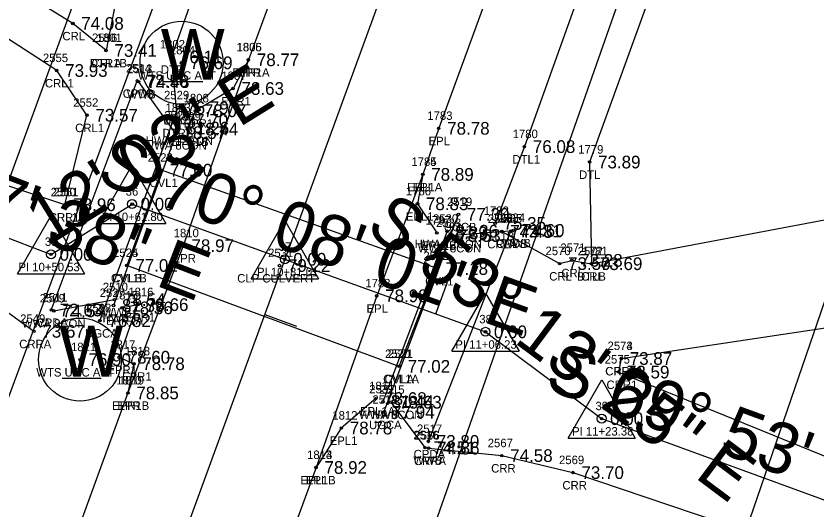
# Model space of a CAD drawing. Extents: x 2139392 to 2143384, y 505395 to 510520.
# Drawn here: x 2140931.1 to 2141025.8, y 509038.2 to 509096.6 of the extents above; entities that cross this region are included whole.
import ezdxf

# ---------------------------------------------------------------- set-up
doc = ezdxf.new("R2010")
doc.units = 0
for name, color, linetype in [('RD_EV_EX_Wetlands', 7, 'Continuous'), ('RD_EX_Bridge', 7, 'Continuous'), ('RD_EX_Bridge_txCode', 7, 'Continuous'), ('RD_EX_Conc', 7, 'Continuous'), ('RD_EX_Conc_txCode', 7, 'Continuous'), ('RD_EX_H2O', 7, 'Continuous'), ('RD_EX_H2O_txCode', 7, 'Continuous'), ('RD_EX_Road', 7, 'Continuous'), ('RD_EX_Road_txCode', 7, 'Continuous'), ('RD_EX_TX_Bridge_ELEV', 7, 'Continuous'), ('RD_EX_TX_Conc_ELEV', 7, 'Continuous'), ('RD_EX_TX_H2O_ELEV', 7, 'Continuous'), ('RD_EX_TX_Road_ELEV', 7, 'Continuous'), ('RD_EX_TX_UT_ELEV', 7, 'Continuous'), ('RD_EX_UT', 7, 'Continuous'), ('RD_EX_UT_txCode', 7, 'Continuous'), ('RD_EX_VEG', 7, 'Continuous'), ('RD_HC_Cl', 7, 'Continuous'), ('RD_HC_Data', 7, 'Continuous'), ('RD_HC_Data_Tic', 7, 'Continuous'), ('RD_HC_Survey_ELEV', 7, 'Continuous'), ('RD_HC_Survey_txCode', 7, 'Continuous'), ('RD_HC_txCode', 7, 'Continuous'), ('RD_SMD_Locator', 7, 'Continuous')]:
    doc.layers.add(name, color=color, linetype=linetype)

msp = doc.modelspace()

# ---------------------------------------------------------------- linework, layer by layer
at = {"layer": 'RD_EV_EX_Wetlands'}
for p, q in [((2141031.306, 509324.164), (2140691.527, 508408.628)), ((2141075.304, 509306.136), (2140751.402, 508384.33))]:
    msp.add_line(p, q, dxfattribs=at)
at = {"layer": 'RD_EX_Bridge'}
for p, q in [((2140949.87, 509082.827), (2140945.533, 509088.869)), ((2140950.236, 509083.385), (2140942.575, 509062.4)), ((2140982.027, 509071.179), (2140974.443, 509051.015)), ((2140982.335, 509070.674), (2140989.888, 509071.278)), ((2140976.362, 509055.202), (2140944.155, 509067.133)), ((2140935.526, 509061.759), (2140942.697, 509063.091)), ((2140975.368, 509050.963), (2140979.412, 509045.581))]:
    msp.add_line(p, q, dxfattribs=at)
msp.add_lwpolyline([(2140976.362, 509055.202), (2140980.845, 509066.769), (2140948.243, 509078.401), (2140944.155, 509067.133)], dxfattribs=at)
at = {"layer": 'RD_EX_Conc'}
for p, q in [((2140935.225, 509061.866), (2140945.395, 509088.954)), ((2140979.81, 509046.325), (2140989.555, 509071.198))]:
    msp.add_line(p, q, dxfattribs=at)
at = {"layer": 'RD_EX_H2O'}
for points in [[(2141109.57, 509415.73), (2141114.373, 509420.617), (2141120.575, 509418.468), (2141123.731, 509414.719), (2141106.652, 509363.278), (2141087.87, 509318.683), (2141079.163, 509303.209), (2141069.29, 509273.889), (2141065.763, 509268.541), (2141032.314, 509171.571), (2140998.874, 509079.361), (2140999.098, 509067.338)], [(2141109.57, 509415.73), (2141094.185, 509368.738), (2141059.481, 509270.332), (2141024.495, 509174.17), (2140991.165, 509081.187), (2140987.702, 509072.107)], [(2141025.18, 509330.004), (2141009.078, 509287.11), (2140976.481, 509188.975), (2140943.34, 509100.907), (2140941.691, 509092.552)], [(2141025.18, 509330.004), (2141033.423, 509326.189), (2141034.031, 509320.599), (2141020.737, 509281.868), (2140983.567, 509187.835), (2140949.439, 509091.794), (2140950.117, 509084.291)], [(2140936.82, 509074.317), (2140939.438, 509084.9), (2140935.86, 509090.184), (2140919.454, 509100.866), (2140920.422, 509116.79)], [(2140941.691, 509092.552), (2140937.766, 509095.748), (2140924.442, 509103.995), (2140920.422, 509116.79)], [(2140936.82, 509074.317), (2140923.191, 509078.832), (2140898.915, 509091.534), (2140893.323, 509095.681)], [(2140933.167, 509059.343), (2140914.479, 509072.895), (2140897.142, 509089.506), (2140893.323, 509095.681)], [(2140988.496, 509071.154), (2140995.331, 509067.351), (2140996.764, 509067.733), (2140999.098, 509067.338), (2141034.377, 509073.973), (2141067.924, 509085.443), (2141090.438, 509074.609), (2141110.471, 509071.641), (2141125.768, 509059.81), (2141130.362, 509054.364)], [(2141002.624, 509056.131), (2141033.302, 509060.757), (2141063.489, 509073.164), (2141074.877, 509066.766), (2141067.89, 509053.225), (2141068.088, 509037.895), (2141072.636, 509017.092)], [(2141002.624, 509056.131), (2141002.292, 509054.528), (2141039.776, 509039.252), (2141058.736, 509017.843), (2141072.636, 509017.092)], [(2140979.842, 509045.531), (2140988.486, 509044.646), (2140996.911, 509042.641), (2141034.466, 509029.98), (2141054.864, 509009.953), (2141076.501, 509008.6), (2141108.933, 509002.878), (2141157.173, 508989.85), (2141167.478, 508991.008), (2141188.812, 509012.46), (2141188.278, 509016.578)]]:
    msp.add_lwpolyline(points, dxfattribs=at)
at = {"layer": 'RD_EX_Road'}
for points in [[(2141086.274, 509371.268), (2141050.416, 509272.831), (2141015.083, 509176.386), (2140981.032, 509083.349), (2140979.152, 509077.9), (2140973.702, 509063.543), (2140966.529, 509043.246), (2140933.444, 508952.985), (2140896.921, 508852.594), (2140862.176, 508757.775), (2140824.897, 508656.318), (2140789.814, 508560.303), (2140766.773, 508496.85), (2140751.904, 508457.035), (2140731.87, 508401.538), (2140727.357, 508390.267)], [(2141052.52, 509348.478), (2141043.476, 509323.884), (2141027.845, 509280.545), (2140992.949, 509184.866), (2140958.528, 509091.45), (2140950.798, 509069.471), (2140944.28, 509052.058), (2140911.452, 508962.099), (2140874.646, 508861.605), (2140839.422, 508765.216), (2140802.376, 508664.564), (2140767.791, 508569.67), (2140744.17, 508504.83), (2140729.493, 508465.071), (2140707.156, 508404.621), (2140705.357, 508398.025)], [(2140958.528, 509091.45), (2140956.714, 509088.061), (2140952.259, 509085.423), (2140951.313, 509083.254)], [(2140979.152, 509077.9), (2140978.521, 509074.421), (2140980.815, 509070.975)], [(2140943.562, 509062.114), (2140945.418, 509062.499), (2140943.254, 509056.281), (2140944.985, 509055.507), (2140944.28, 509052.058)], [(2140973.585, 509051.39), (2140969.517, 509047.91), (2140966.529, 509043.246)]]:
    msp.add_lwpolyline(points, dxfattribs=at)
at = {"layer": 'RD_EX_UT'}
for p, q in [((2140948.502, 509088.885), (2140953.131, 509088.885)), ((2140940.967, 509060.604), (2140950.18, 509085.778)), ((2140974.537, 509049.783), (2140983.367, 509073.169)), ((2140936.488, 509053.791), (2140941.117, 509053.791))]:
    msp.add_line(p, q, dxfattribs=at)
for centre in [(2140950.63, 509091.093), (2140938.616, 509055.999)]:
    msp.add_circle(centre, 4.908, dxfattribs=at)
at = {"layer": 'RD_EX_VEG'}
for points in [[(2140900.084, 509397.36), (2141021.293, 509326.195), (2140852.613, 508865.264), (2140689.341, 508413.458), (2140624.535, 508226.483), (2140606.41, 508171.784), (2140591.23, 508116.672), (2140558.821, 507962.773), (2140538.778, 507709.071), (2140410.608, 507724.882)], [(2141197.739, 509262.45), (2141108.657, 509301.696), (2140947.303, 508831.924), (2140798.257, 508440.006), (2140718.897, 508193.899), (2140671.921, 508048.021), (2140772.34, 507989.744)]]:
    msp.add_lwpolyline(points, dxfattribs=at)
at = {"layer": 'RD_HC_Cl'}
for p, q in [((2141333.53, 510081.693), (2140670.514, 508268.365)), ((2140918.963, 509074.69), (2140935.196, 509068.446)), ((2140935.196, 509068.446), (2140944.777, 509074.386)), ((2140944.777, 509074.386), (2140986.562, 509059.288)), ((2140986.562, 509059.288), (2141000.301, 509049.019)), ((2141000.301, 509049.019), (2141036.935, 509035.612))]:
    msp.add_line(p, q, dxfattribs=at)
at = {"layer": 'RD_HC_Data'}
for p, q in [((2140940.806, 509072.094), (2140944.778, 509078.973)), ((2140944.778, 509078.973), (2140948.747, 509072.094)), ((2140931.225, 509066.153), (2140935.197, 509073.033)), ((2140935.197, 509073.033), (2140939.166, 509066.153)), ((2140940.806, 509072.094), (2140948.747, 509072.094)), ((2140958.867, 509065.568), (2140962.839, 509072.447)), ((2140962.839, 509072.447), (2140966.807, 509065.568)), ((2140931.225, 509066.153), (2140939.166, 509066.153)), ((2140958.867, 509065.568), (2140966.807, 509065.568)), ((2140982.591, 509056.995), (2140986.563, 509063.875)), ((2140986.563, 509063.875), (2140990.532, 509056.995)), ((2140982.591, 509056.995), (2140990.532, 509056.995)), ((2140996.33, 509046.726), (2141000.302, 509053.606)), ((2141000.302, 509053.606), (2141004.271, 509046.726)), ((2140996.33, 509046.726), (2141004.271, 509046.726))]:
    msp.add_line(p, q, dxfattribs=at)
for centre in [(2140944.777, 509074.386), (2140935.196, 509068.446), (2140962.837, 509067.861), (2140986.562, 509059.288), (2141000.301, 509049.019)]:
    msp.add_circle(centre, 0.529, dxfattribs=at)
at = {"layer": 'RD_HC_Data_Tic'}
for p, q in [((2140980.701, 509061.406), (2140982.061, 509065.168)), ((2140960.454, 509061.342), (2140964.211, 509059.968))]:
    msp.add_line(p, q, dxfattribs=at)
at = {"layer": 'RD_SMD_Locator'}
for centre in [(2140937.766, 509095.748), (2140941.691, 509092.552), (2140941.691, 509092.552), (2140949.439, 509091.794), (2140950.63, 509091.093), (2140958.528, 509091.45), (2140958.528, 509091.45), (2140935.86, 509090.184), (2140945.395, 509088.954), (2140945.533, 509088.869), (2140956.714, 509088.061), (2140950.18, 509085.778), (2140952.259, 509085.423), (2140939.438, 509084.9), (2140950.117, 509084.291), (2140950.236, 509083.385), (2140951.313, 509083.254), (2140981.032, 509083.349), (2140949.87, 509082.827), (2140991.165, 509081.187), (2140998.874, 509079.361), (2140948.243, 509078.401), (2140979.152, 509077.9), (2140979.152, 509077.9), (2140936.82, 509074.317), (2140936.82, 509074.317), (2140944.777, 509074.386), (2140978.521, 509074.421), (2140983.367, 509073.169), (2140987.702, 509072.107), (2140980.815, 509070.975), (2140982.027, 509071.179), (2140988.496, 509071.154), (2140989.555, 509071.198), (2140989.888, 509071.278), (2140982.335, 509070.674), (2140950.798, 509069.471), (2140935.196, 509068.446), (2140944.155, 509067.133), (2140944.155, 509067.133), (2140962.206, 509067.119), (2140962.837, 509067.861), (2140995.331, 509067.351), (2140996.764, 509067.733), (2140999.098, 509067.338), (2140999.098, 509067.338), (2140980.845, 509066.769), (2140973.702, 509063.543), (2140942.575, 509062.4), (2140942.697, 509063.091), (2140945.418, 509062.499), (2140935.225, 509061.866), (2140935.526, 509061.759), (2140943.562, 509062.114), (2140940.967, 509060.604), (2140933.167, 509059.343), (2140986.562, 509059.288), (2140938.616, 509055.999), (2140943.254, 509056.281), (2141002.624, 509056.131), (2141002.624, 509056.131), (2140944.985, 509055.507), (2140976.362, 509055.202), (2140976.362, 509055.202), (2141002.292, 509054.528), (2140944.28, 509052.058), (2140944.28, 509052.058), (2140973.585, 509051.39), (2140974.443, 509051.015), (2140975.368, 509050.963), (2140974.537, 509049.783), (2141000.301, 509049.019), (2140969.517, 509047.91), (2140979.81, 509046.325), (2140979.412, 509045.581), (2140979.842, 509045.531), (2140988.486, 509044.646), (2140966.529, 509043.246), (2140966.529, 509043.246), (2140996.911, 509042.641)]:
    msp.add_circle(centre, 0.15, dxfattribs=at)

# ---------------------------------------------------------------- texts
at = {"layer": 'RD_EX_Bridge_txCode'}
for s, p in [('2513', (2140944.187, 509089.869)), ('WWB', (2140944.155, 509086.869)), ('2526', (2140948.583, 509084.385)), ('2512', (2140948.524, 509083.827)), ('HWA 12CON', (2140946.394, 509081.385)), ('WWA 8CON', (2140946.106, 509080.827)), ('2523', (2140946.613, 509079.401)), ('CVL1', (2140946.833, 509076.401)), ('2530', (2140980.358, 509072.179)), ('2534', (2140988.258, 509072.278)), ('2533', (2140980.705, 509071.674)), ('HWA 12CON', (2140978.184, 509069.179)), ('WWB', (2140988.51, 509069.278)), ('2524', (2140942.525, 509068.133)), ('2525', (2140942.525, 509068.133)), ('WWA 8CON', (2140978.571, 509068.674)), ('2522', (2140979.215, 509067.769)), ('CVL1B', (2140942.273, 509065.133)), ('CVLB', (2140942.438, 509065.133)), ('CVL1', (2140979.435, 509064.769)), ('2527', (2140940.945, 509063.4)), ('2510', (2140941.311, 509064.091)), ('2509', (2140933.857, 509062.759)), ('WWB', (2140941.319, 509061.091)), ('WWA 8CON', (2140931.762, 509059.759)), ('HWB', (2140941.283, 509060.4)), ('2520', (2140974.693, 509056.202)), ('2521', (2140975.016, 509056.202)), ('CVL1A', (2140974.464, 509053.202)), ('CVLA', (2140974.63, 509053.202)), ('2532', (2140972.813, 509052.015)), ('2515', (2140974.021, 509051.963)), ('WWA 8CON', (2140971.604, 509048.963)), ('HWB', (2140973.151, 509049.015)), ('2516', (2140978.042, 509046.581)), ('WWB', (2140978.034, 509043.581))]:
    msp.add_text(s, height=1, dxfattribs=at).set_placement(p)
at = {"layer": 'RD_EX_Conc_txCode'}
for s, p in [('2514', (2140944.049, 509089.954)), ('CPDB', (2140943.671, 509086.954)), ('2535', (2140987.926, 509072.198)), ('CPDB', (2140987.831, 509069.198)), ('2511', (2140934.162, 509062.866)), ('CPDA', (2140933.485, 509059.866)), ('2517', (2140978.464, 509047.325)), ('CPDA', (2140978.07, 509044.325))]:
    msp.add_text(s, height=1, dxfattribs=at).set_placement(p)
at = {"layer": 'RD_EX_H2O_txCode'}
for s, p in [('CRL', (2140936.538, 509093.748)), ('2556', (2140940.038, 509093.552)), ('1801', (2140940.589, 509093.552)), ('1802', (2140948.053, 509092.794)), ('2555', (2140934.23, 509091.184)), ('DTR1B', (2140939.786, 509090.552)), ('CRLA', (2140939.975, 509090.552)), ('DTR', (2140948.172, 509089.794)), ('CRL1', (2140934.466, 509088.184)), ('2552', (2140937.808, 509085.9)), ('1803', (2140948.731, 509085.291)), ('CRL1', (2140938.044, 509082.9)), ('DTRB', (2140948.376, 509082.291)), ('1780', (2140989.779, 509082.187)), ('1779', (2140997.528, 509080.361)), ('DTL1', (2140989.756, 509079.187)), ('DTL', (2140997.63, 509077.361)), ('2550', (2140935.151, 509075.317)), ('2551', (2140935.474, 509075.317)), ('1782', (2140986.356, 509073.107)), ('CRR1A', (2140934.915, 509072.317)), ('CRL1A', (2140934.938, 509072.317)), ('2568', (2140986.842, 509072.154)), ('DTL1B', (2140985.821, 509070.107)), ('CRLA', (2140986.779, 509069.154)), ('2570', (2140993.661, 509068.351)), ('2571', (2140995.418, 509068.733)), ('2572', (2140997.468, 509068.338)), ('1781', (2140998.035, 509068.338)), ('CRL', (2140994.102, 509065.351)), ('CRL', (2140995.536, 509065.733)), ('DTLB', (2140997.381, 509065.338)), ('CRL', (2140997.87, 509065.338)), ('2549', (2140931.537, 509060.343)), ('CRRA', (2140931.427, 509057.343)), ('2573', (2141000.994, 509057.131)), ('2574', (2141000.994, 509057.131)), ('2575', (2141000.662, 509055.528)), ('CRR1A', (2141000.718, 509054.131)), ('CRL1A', (2141000.742, 509054.131)), ('CRR1', (2141000.875, 509052.528)), ('2566', (2140978.165, 509046.531)), ('2567', (2140986.832, 509045.646)), ('CRRA', (2140978.102, 509043.531)), ('2569', (2140995.258, 509043.641)), ('CRR', (2140987.234, 509042.646)), ('CRR', (2140995.659, 509040.641))]:
    msp.add_text(s, height=1, dxfattribs=at).set_placement(p)
at = {"layer": 'RD_EX_Road_txCode'}
for s, p in [('1806', (2140957.118, 509092.45)), ('1805', (2140957.142, 509092.45)), ('1807', (2140955.328, 509089.061)), ('EPR1A', (2140956.646, 509089.45)), ('EPR', (2140957.299, 509089.45)), ('1808', (2140950.873, 509086.423)), ('EPR1', (2140955.32, 509086.061)), ('1809', (2140949.928, 509084.254)), ('1783', (2140979.686, 509084.349)), ('EPR1', (2140950.865, 509083.423)), ('EPR1B', (2140949.447, 509081.254)), ('EPL', (2140979.828, 509081.349)), ('1784', (2140977.806, 509078.9)), ('1785', (2140977.806, 509078.9)), ('EPL1A', (2140977.294, 509075.9)), ('EPL', (2140977.947, 509075.9)), ('1786', (2140977.151, 509075.421)), ('EPL1', (2140977.151, 509072.421)), ('1787', (2140979.468, 509071.975)), ('1810', (2140949.696, 509070.471)), ('EPL1B', (2140978.972, 509068.975)), ('EPR', (2140949.57, 509067.471)), ('1788', (2140972.355, 509064.543)), ('1816', (2140944.331, 509063.499)), ('1815', (2140942.499, 509063.114)), ('EPL', (2140972.497, 509061.543)), ('EPR1A', (2140941.68, 509060.114)), ('EPR1', (2140944.024, 509060.499)), ('1817', (2140942.191, 509057.281)), ('1818', (2140943.922, 509056.507)), ('EPR1', (2140941.86, 509054.281)), ('1820', (2140942.894, 509053.058)), ('1819', (2140943.217, 509053.058)), ('EPR1', (2140943.592, 509053.507)), ('1811', (2140972.805, 509052.39)), ('EPR1B', (2140942.414, 509050.058)), ('EPR', (2140943.051, 509050.058)), ('EPL1A', (2140971.727, 509049.39)), ('1812', (2140968.454, 509048.91)), ('EPL1', (2140968.147, 509045.91)), ('1813', (2140965.466, 509044.246)), ('1814', (2140965.466, 509044.246)), ('EPL1B', (2140964.686, 509041.246)), ('EPL', (2140965.324, 509041.246))]:
    msp.add_text(s, height=1, dxfattribs=at).set_placement(p)
at = {"layer": 'RD_EX_TX_Bridge_ELEV'}
for s, p in [('74.48', (2140946.533, 509088.119)), ('78.57', (2140950.87, 509082.077)), ('81.26', (2140951.236, 509082.635)), ('77.00', (2140949.243, 509077.651)), ('81.36', (2140983.027, 509070.429)), ('74.60', (2140990.888, 509070.528)), ('78.53', (2140983.335, 509069.924)), ('77.02', (2140945.155, 509066.383)), ('77.02', (2140945.155, 509066.383)), ('77.18', (2140981.845, 509066.019)), ('78.54', (2140943.697, 509062.341)), ('74.54', (2140936.526, 509061.009)), ('81.39', (2140943.575, 509061.65)), ('77.02', (2140977.362, 509054.452)), ('77.02', (2140977.362, 509054.452)), ('81.44', (2140975.443, 509050.265)), ('78.63', (2140976.368, 509050.213)), ('74.51', (2140980.412, 509044.831))]:
    msp.add_text(s, height=1.5, dxfattribs=at).set_placement(p)
at = {"layer": 'RD_EX_TX_Conc_ELEV'}
for s, p in [('72.56', (2140946.395, 509088.204)), ('72.31', (2140990.555, 509070.448)), ('72.63', (2140936.225, 509061.116)), ('73.80', (2140980.81, 509045.575))]:
    msp.add_text(s, height=1.5, dxfattribs=at).set_placement(p)
at = {"layer": 'RD_EX_TX_H2O_ELEV'}
for s, p in [('74.08', (2140938.766, 509094.998)), ('73.41', (2140942.691, 509091.802)), ('73.41', (2140942.691, 509091.802)), ('76.11', (2140950.439, 509091.044)), ('73.93', (2140936.86, 509089.434)), ('73.57', (2140940.438, 509084.15)), ('77.70', (2140951.117, 509083.541)), ('76.08', (2140992.165, 509080.437)), ('73.89', (2140999.874, 509078.611)), ('73.96', (2140937.82, 509073.567)), ('73.96', (2140937.82, 509073.567)), ('75.35', (2140988.702, 509071.357)), ('74.48', (2140989.496, 509070.404)), ('73.28', (2140997.764, 509066.983)), ('73.50', (2140996.331, 509066.601)), ('73.69', (2141000.098, 509066.588)), ('73.69', (2141000.098, 509066.588)), ('73.67', (2140934.167, 509058.593)), ('73.87', (2141003.624, 509055.381)), ('73.87', (2141003.624, 509055.381)), ('73.59', (2141003.292, 509053.778)), ('74.86', (2140980.842, 509044.781)), ('74.58', (2140989.486, 509043.896)), ('73.70', (2140997.911, 509041.891))]:
    msp.add_text(s, height=1.5, dxfattribs=at).set_placement(p)
at = {"layer": 'RD_EX_TX_Road_ELEV'}
for s, p in [('78.77', (2140959.528, 509090.7)), ('78.77', (2140959.528, 509090.7)), ('78.63', (2140957.714, 509087.311)), ('78.07', (2140953.259, 509084.673)), ('78.44', (2140952.313, 509082.504)), ('78.78', (2140982.032, 509082.599)), ('78.89', (2140980.152, 509077.15)), ('78.89', (2140980.152, 509077.15)), ('78.83', (2140979.521, 509073.671)), ('78.39', (2140981.815, 509070.225)), ('78.97', (2140951.798, 509068.721)), ('78.98', (2140974.702, 509062.793)), ('78.36', (2140944.562, 509061.364)), ('78.66', (2140946.418, 509061.749)), ('78.60', (2140944.254, 509055.531)), ('78.78', (2140945.985, 509054.757)), ('78.85', (2140945.28, 509051.308)), ('78.85', (2140945.28, 509051.308)), ('78.68', (2140974.585, 509050.64)), ('78.78', (2140970.517, 509047.16)), ('78.92', (2140967.529, 509042.496)), ('78.92', (2140967.529, 509042.496))]:
    msp.add_text(s, height=1.5, dxfattribs=at).set_placement(p)
at = {"layer": 'RD_EX_TX_UT_ELEV'}
for s, p in [('76.69', (2140951.63, 509090.343)), ('76.79', (2140951.18, 509085.028)), ('77.30', (2140984.367, 509072.419)), ('76.82', (2140941.967, 509059.854)), ('76.90', (2140939.616, 509055.249)), ('77.94', (2140975.537, 509049.033))]:
    msp.add_text(s, height=1.5, dxfattribs=at).set_placement(p)
at = {"layer": 'RD_EX_UT'}
for p in [(2140948.165, 509089.092), (2140936.151, 509053.998)]:
    msp.add_text('W', height=6, dxfattribs=at).set_placement(p)
at = {"layer": 'RD_EX_UT_txCode'}
for s, p in [('1804', (2140949.244, 509092.093)), ('WTS UGC ATT', (2140945.464, 509089.093)), ('2529', (2140948.551, 509086.778)), ('UGCB', (2140948.448, 509083.778)), ('2519', (2140982.02, 509074.169)), ('UGCB', (2140981.634, 509071.169)), ('2528', (2140939.337, 509061.604)), ('UGCA', (2140939.219, 509058.604)), ('1821', (2140937.553, 509056.999)), ('WTS UGC ATT', (2140933.451, 509053.999)), ('2518', (2140973.19, 509050.783)), ('UGCA', (2140972.788, 509047.783))]:
    msp.add_text(s, height=1, dxfattribs=at).set_placement(p)
at = {"layer": 'RD_HC_Data'}
for s, rotation, p in [('N 58%%d 12\' 03" E', 31.79905, (2140915.68, 509057.523)), ('S 68%%d 57\' 38" E', 338.96055, (2140902.012, 509082.282)), ('S 70%%d 08\' 01" E', 340.13358, (2140940.388, 509077.036)), ('S 53%%d 13\' 25" E', 323.2237, (2140972.209, 509071.265)), ('S 69%%d 53\' 54" E', 339.8984, (2140993.378, 509052.617))]:
    msp.add_text(s, height=6, rotation=rotation, dxfattribs=at).set_placement(p)
at = {"layer": 'RD_HC_Survey_ELEV'}
for s, p in [('0.00', (2140945.777, 509073.636)), ('0.00', (2140936.196, 509067.696)), ('0.00', (2140963.837, 509067.111)), ('79.22', (2140963.206, 509066.369)), ('0.00', (2140987.562, 509058.538)), ('0.00', (2141001.301, 509048.269))]:
    msp.add_text(s, height=1.5, dxfattribs=at).set_placement(p)
at = {"layer": 'RD_HC_Survey_txCode'}
for s, p in [('2531', (2140960.859, 509068.119)), ('CLP CULVERT', (2140957.206, 509065.119))]:
    msp.add_text(s, height=1, dxfattribs=at).set_placement(p)
at = {"layer": 'RD_HC_txCode'}
for s, p in [('36', (2140944.021, 509075.386)), ('PI 10+61.80', (2140941.179, 509072.386)), ('35', (2140934.463, 509069.446)), ('37', (2140962.105, 509068.861)), ('PI 10+50.53', (2140931.337, 509066.446)), ('PI 10+81.01', (2140959.546, 509065.861)), ('38', (2140985.83, 509060.288)), ('PI 11+06.23', (2140983.003, 509057.288)), ('39', (2140999.569, 509050.019)), ('PI 11+23.38', (2140996.805, 509047.019))]:
    msp.add_text(s, height=1, dxfattribs=at).set_placement(p)

doc.saveas('drawing.dxf')
